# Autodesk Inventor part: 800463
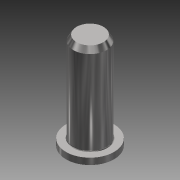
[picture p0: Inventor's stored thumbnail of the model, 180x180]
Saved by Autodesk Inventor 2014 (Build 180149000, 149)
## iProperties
Created: 2007-10
Part Number: 800463
Document SubType Name: Modeling
Designer: JC
Density: 7.84 g/cm^3
Mass: 9.36188 g
Surface Area: 7.72974 cm^2
Volume: 1.19412 cm^3
Material: Steel, High Strength Low Alloy
Description: PIVOT PIN
Appearance: Steel - Polished
Component Category: Fasteners
Author: JC
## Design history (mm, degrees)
workplane "Work Plane2"
sketch "Sketch1"
  geometry: L1 (614.557, 0)-(-3687.344, 0) reference; L2 (0, -83.277)-(0, 499.66) reference; C1 r 3.2 at (-3068.836, 412.433); C2 r 3.95 at (-3068.836, 412.433); 1 further point
  constraints: 2 centre point, 1 coincident
  dimensions: "d2" = 6.40001 diameter of C1; "d3" = 412.43322 distance from line of L1 C1.centre; "d4" = 3068.83645 distance from line of L2 C1.centre; "d7" = 7.90001 diameter of C2
extrude "Extrusion1" new body sketch "Sketch1" distance "d5" = 21.4; taper "d6" = 0 deg
sketch "Sketch2"
  geometry: C1 r 3.95 at (0, 0) reference; C2 r 5.715 at (0, 0)
  constraints: 1 centre point, 1 coincident
  dimensions: "d8" = 11.43002 diameter of C2
extrude "Extrusion2" join sketch "Sketch2" distance "d9" = 1.52; taper "d10" = 0 deg
fillet "Fillet1" dims "d11" = 0.25
chamfer "Chamfer2" distance "d15" = 1.27; stored, may be unused: second distance "d16" = 0.7554, angle "d17" = 45 deg
body "Solid1"
other parameters: "d1" = 494.53487
